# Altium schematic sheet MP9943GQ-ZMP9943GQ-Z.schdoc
size 127 x 101 mm
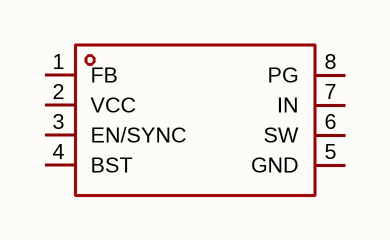
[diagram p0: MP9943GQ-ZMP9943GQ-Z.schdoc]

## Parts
U?  mp9943gq-z  [QFN-8_L3.0-W3.0-P0.65-BL]  (value not drawn)

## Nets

Not connected (* = marked no-connect by the designer): U? 1(FB) 2(VCC) 3(EN/SYNC) 4(BST) 5(GND) 6(SW) 7(IN) 8(PG)

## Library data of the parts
U? = mp9943gq-z: 功能类型:降压型;工作电压:4V~36V;输出电压:800mV~28.5V;输出电流:3A;输出类型:可调;; Manufacturer: MPS(芯源); AddInBom: yes; ModelId: 75d54807ab0b4de5965aa3293c83a045; ModelTransform: 118.8974,118.11,0,90,0,0,0,0,0; Function: 降压型; Voltage - Supply: 4V~36V; Output Current: 3A; Frequency - Switching: 410kHz；200kHz~2.2MHz; Synchronous Rectifier: 是; Number of Outputs: 1; Topology: 降压式; Quiescent Current: 500uA; Switch tube (built-in/external): 内置; Output Type: 可调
